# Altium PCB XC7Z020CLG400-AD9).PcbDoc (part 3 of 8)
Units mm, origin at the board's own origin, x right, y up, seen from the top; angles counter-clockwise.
Board outline 38 x 38 mm, 14 copper layers (Top Layer, GND02, ART03, PWR04, ART05, GND06, ART07, ART08, PWR09, ART10, GND11, ART12, PWR13, Bottom Layer); 276 components, 302 nets, 1684 pads, 1576 vias.
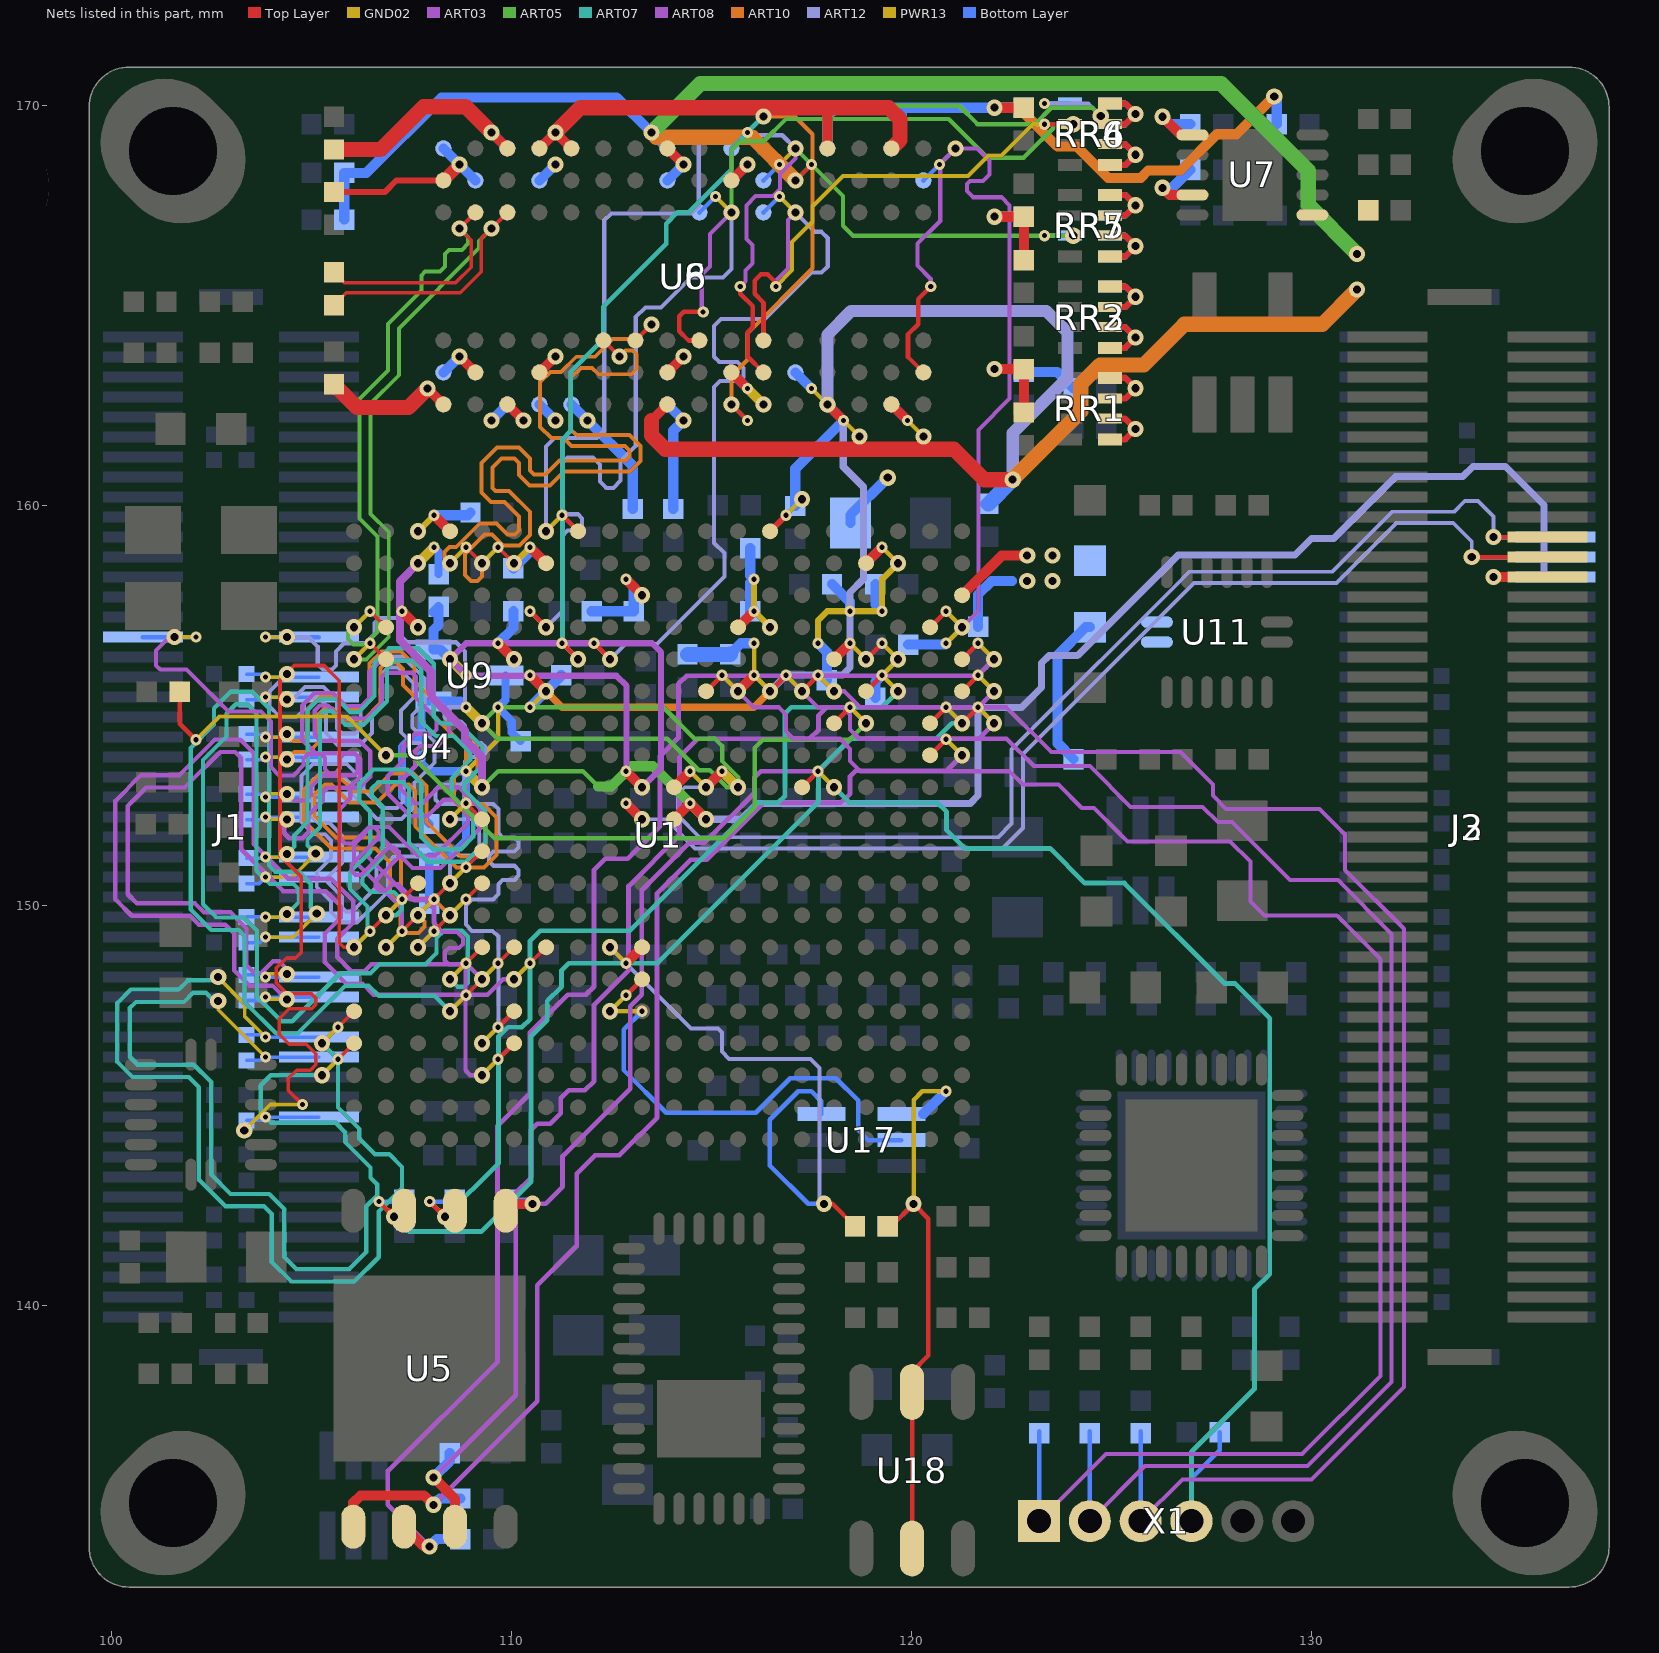
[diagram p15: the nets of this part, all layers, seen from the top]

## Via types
v1: diameter 0.406, hole 0.203, GND02 to PWR13, 466 vias
v2: diameter 0.279, hole 0.127, Top Layer to GND02, tented top, 373 vias
v3: diameter 0.406, hole 0.203, Top Layer to Bottom Layer, 324 vias
v4: diameter 0.279, hole 0.127, PWR13 to Bottom Layer, 207 vias
v5: diameter 0.279, hole 0.127, Top Layer to ART03, tented top, 41 vias
v6: diameter 0.279, hole 0.127, Top Layer to ART03, 40 vias
v7: diameter 0.279, hole 0.127, PWR13 to Bottom Layer, tented bottom, 39 vias
v8: diameter 0.279, hole 0.127, ART12 to Bottom Layer, 30 vias
v9: diameter 0.279, hole 0.127, Top Layer to GND02, 20 vias
v10: diameter 0.406, hole 0.203, Top Layer to Bottom Layer, tented both sides, 16 vias
v11: diameter 0.406, hole 0.203, ART03 to ART12, 11 vias
v12: diameter 0.406, hole 0.203, Top Layer to Bottom Layer, tented top, 9 vias

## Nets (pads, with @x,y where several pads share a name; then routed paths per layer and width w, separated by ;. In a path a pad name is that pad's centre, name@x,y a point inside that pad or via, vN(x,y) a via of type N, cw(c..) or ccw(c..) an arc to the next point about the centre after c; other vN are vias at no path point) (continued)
ADDR3-DQS2_N: U1.T2 U8.G3 | length 18.3
  Top Layer w0.089: v2(108.865,158.965) U1.T2@109.265,158.565 ; U8.G3@113.1,164.135 v3(113.5,164.535)
  ART10 w0.099: v1(108.465,158.565) 108.331,158.699 108.331,158.852 108.452,158.973 108.62,158.973 109.207,159.56 109.629,159.56 109.906,159.283 110.084,159.283 110.188,159.388 110.188,159.738 109.827,160.099 109.486,160.099 109.248,160.337 109.248,161.074 109.636,161.463 110.19,161.463 110.465,161.188 110.465,160.884 110.566,160.782 110.846,160.782 111.201,161.138 112.852,161.138 112.954,161.239 112.954,161.381 112.839,161.496 111.505,161.496 111.305,161.696 110.998,161.696 110.719,161.976 110.719,163.093 110.973,163.347 111.238,163.347 111.619,163.728 112.083,163.728 112.521,164.167 113.132,164.167 v3(113.5,164.535)
  GND02 w0.109: v1(108.465,158.565) v2(108.865,158.965)
ADDR3-DQS2_P: U1.R2 U8.F3 | length 18.3
  Top Layer w0.089: v2(109.665,158.965) U1.R2@110.065,158.565 ; U8.F3@112.3,164.135 v3(112.7,163.735)
  ART10 w0.099: v1(109.265,158.565) 109.265,158.236 109.149,158.121 108.986,158.121 108.839,158.267 108.839,158.801 109.321,159.283 109.514,159.283 109.791,159.007 110.198,159.007 110.465,159.273 110.465,159.853 109.942,160.376 109.601,160.376 109.525,160.452 109.525,160.96 109.751,161.186 110.076,161.186 110.188,161.074 110.188,160.769 110.452,160.505 110.96,160.505 111.316,160.861 112.967,160.861 113.231,161.125 113.231,161.496 112.954,161.773 111.622,161.773 111.481,161.914 111.481,163.195 111.735,163.449 112.014,163.449 112.172,163.291 112.999,163.291 113.132,163.424 113.132,163.779 113.03,163.881 112.846,163.881 v3(112.7,163.735)
  GND02 w0.109: v1(109.265,158.565) v2(109.665,158.965)
ADDR3-DQS3_N: R98.2 U1.W4 U8.B7 | length 19.7
  Top Layer w0.089: R98.2@105.562,165.84 105.82,165.583 108.61,165.583 108.991,165.964 108.991,166.644 v3(108.7,166.935) U8.B7@109.1,167.335 ; v2(106.465,157.365) U1.W4@106.865,156.965
  ART05 w0.099: v1(106.065,156.965) 105.918,156.818 105.918,156.667 106.045,156.54 106.35,156.54 106.655,156.845 106.655,159.233 106.2,159.687 106.2,162.672 106.909,163.38 106.909,164.552 107.747,165.39 107.747,165.76 107.841,165.855 108.211,165.855 108.337,165.98 108.337,166.299 108.438,166.401 108.758,166.401 108.915,166.558 ; v3(108.7,166.935) 108.915,166.72 108.915,166.558 ; 108.915,166.562 108.915,166.558
  GND02 w0.109: v1(106.065,156.965) v2(106.465,157.365)
ADDR3-DQS3_P: R98.1 U1.W5 U8.C7 | length 19.7
  Top Layer w0.089: R98.1@105.562,165.02 105.868,165.326 108.717,165.326 109.248,165.857 109.248,166.683 v3(109.5,166.935) U8.C7@109.9,167.335 ; v2(106.465,156.565) U1.W5@106.865,156.165
  ART05 w0.099: v1(106.065,156.165) 106.37,156.165 106.931,156.727 106.931,159.347 106.477,159.802 106.477,162.557 107.185,163.266 107.185,164.437 109.192,166.444 109.192,166.627 v3(109.5,166.935)
  GND02 w0.109: v1(106.065,156.165) v2(106.465,156.565)
ADDR3-ODT0: RR6.8 U1.N5 U6.K1 U8.K1 | length 39.5
  Top Layer w0.114: v2(111.265,156.565) v1(111.665,156.165) ; v1(115.5,162.535) v2(115.9,162.135)
  ART05 w0.109: v1(116.3,169.735) 116.567,170.002 121.191,170.002 121.649,169.545 123.088,169.545 123.495,169.951 124.528,169.951 v11(124.731,169.748)
  ART10 w0.109: v1(115.5,162.535) 115.5,163.252 115.9,163.652 115.9,164.313 117.526,165.938 117.526,169.291 117.082,169.735 v1(116.3,169.735)
  ART12 w0.102: v8(123.325,170.061) 124.419,170.061 v11(124.731,169.748)
  GND02 w0.109: v2(111.265,156.565) v1(111.665,156.165) ; v1(115.5,162.535) v2(115.9,162.135)
  ART07 w0.119: v1(111.665,156.165) 111.277,156.553 111.277,161.671 111.481,161.874 111.481,163.347 112.293,164.16 112.293,164.973 113.868,166.548 113.868,167.056 114.148,167.335 114.427,167.335 115.494,168.402 115.494,168.929 v1(116.3,169.735)
  PWR13 w0.114: v7(115.9,169.335) v1(116.3,169.735)
  Bottom Layer w0.114: U6.K1@115.5,168.935 v7(115.9,169.335) ; v8(123.325,170.061) RR6.8@123.96,170.061
ADDR3-RAS: RR6.7 U1.P4 U6.J3 U8.J3 | length 34.9
  Top Layer w0.114: v2(110.465,157.365) v1(110.865,156.965) ; U8.J3@114.7,164.135 114.427,164.135 114.198,164.363 114.198,164.744 114.305,164.851 v5(114.792,164.851)
  ART03 w0.102: v5@114.757,164.851 114.757,165.786 114.96,165.989 114.96,166.795 v1(115.5,167.335)
  ART05 w0.109: v1(115.5,167.335) 115.5,168.891 115.722,169.113 116.307,169.113 116.865,169.672 120.929,169.672 121.895,168.707 122.809,168.707 123.643,169.541 v11(124.046,169.541)
  ART12 w0.102: v1(110.865,156.965) 111.258,157.358 111.258,159.239 111.404,159.385 111.658,159.385 111.76,159.487 111.76,159.69 111.658,159.791 111.385,159.791 111.258,159.918 111.258,161.067 111.404,161.214 112.039,161.214 112.217,161.036 112.217,160.604 112.37,160.452 112.547,160.452 112.725,160.63 112.725,161.112 113.106,161.493 113.106,164.719 113.348,164.961 113.734,164.961 114.484,165.71 115.291,165.71 115.5,165.919 v1(115.5,167.335) ; v8(123.325,169.541) v11(124.046,169.541)
  GND02 w0.109: v2(110.465,157.365) v1(110.865,156.965)
  PWR13 w0.114: v7(115.1,167.735) v1(115.5,167.335)
  Bottom Layer w0.114: U6.J3@114.7,167.335 v7(115.1,167.735) ; v8(123.325,169.541) RR6.7@123.96,169.541
ADDR3-RESET: R67.1 U1.B4 U6.T2 U8.T2 | length 24.7
  Top Layer w0.114: U8.T2@120.3,163.335 119.913,163.722 119.913,164.287 120.167,164.541 120.167,165.171 v5(120.482,165.486) ; U1.B4@120.465,156.965 v2(120.865,157.365)
  ART03 w0.102: v5(120.482,165.486) 120.482,165.674 120.148,166.008 120.148,166.554 120.719,167.125 120.719,168.555 v1(121.1,168.935) 121.641,168.935 121.955,168.621 121.955,168.284 121.793,168.123 121.463,168.123 121.387,168.046 121.387,167.869 121.539,167.716 122.25,167.716 122.453,167.513 122.453,162.681 121.672,161.9 121.672,157.372 v1(121.265,156.965)
  GND02 w0.109: v2(120.865,157.365) v1(121.265,156.965)
  PWR13 w0.114: v7(120.7,168.535) v1(121.1,168.935) ; v4(120.865,156.565) v1(121.265,156.965)
  Bottom Layer w0.114: U6.T2@120.3,168.135 v7(120.7,168.535)
  Bottom Layer w0.254: R67.1@119.917,156.532 120.832,156.532 v4(120.865,156.565)
ADDR3-S0: RR5.6 U1.N1 U6.L2 U8.L2 | length 34.5
  Top Layer w0.114: v2(111.265,159.765) U1.N1@111.665,159.365 ; v5(115.719,165.486) 115.719,165.306 116.037,164.989 116.037,164.475 115.91,164.348 115.91,163.725 U8.L2@116.3,163.335
  ART03 w0.102: v5(115.719,165.486) 115.849,165.615 115.849,165.887 116.027,166.065 116.027,166.522 115.875,166.675 115.875,167.513 116.103,167.742 116.535,167.742 116.713,167.919 116.713,168.3 117.1,168.687 v1(117.1,168.935)
  ART05 w0.109: v1(117.1,168.935) 118.288,167.747 118.288,167.005 118.538,166.755 v11(124.046,166.755)
  ART12 w0.102: v1(110.865,159.365) 110.865,161.487 111.074,161.696 112.141,161.696 112.319,161.874 112.319,167.132 112.497,167.31 114.503,167.31 114.681,167.488 114.681,169.088 114.859,169.266 116.769,169.266 v1(117.1,168.935) ; v8(123.325,166.755) v11(124.046,166.755)
  GND02 w0.109: v1(110.865,159.365) v2(111.265,159.765)
  PWR13 w0.114: v7(116.7,168.535) v1(117.1,168.935)
  Bottom Layer w0.114: U6.L2@116.3,168.135 v7(116.7,168.535) ; v8(123.325,166.755) RR5.6@123.96,166.755
ADDR3-WE: RR4.6 U1.M5 U6.L3 U8.L3 | length 32.8
  Top Layer w0.114: v2(112.065,156.565) v1(112.465,156.165) ; U8.L3@116.3,164.135 116.3,165.081 116.078,165.303 116.078,165.633 116.23,165.786 116.408,165.786 116.608,165.586 v5(116.608,165.486) ; v6(123.325,169.541) RR4.6@123.96,169.541
  ART03 w0.102: v5(116.608,165.486) 116.608,165.63 116.916,165.938 116.916,167.151 v1(117.1,167.335)
  ART12 w0.102: v1(112.465,156.165) 112.845,156.546 113.638,156.546 115.322,158.23 115.322,158.82 115.068,159.074 115.068,162.972 115.214,163.119 115.697,163.119 115.799,163.22 115.799,163.449 115.646,163.601 115.195,163.601 115.068,163.728 115.068,164.496 115.24,164.668 116.332,164.668 117.5,165.837 117.754,165.837 117.907,165.989 117.907,166.7 117.754,166.853 117.582,166.853 v1(117.1,167.335)
  GND02 w0.102: v5(116.608,165.486) 117.018,165.895 117.018,166.599 117.526,167.107 117.526,167.488 118.288,168.25 121.412,168.25 121.92,168.758 122.25,168.758 123.034,169.541 v6(123.325,169.541)
  GND02 w0.109: v2(112.065,156.565) v1(112.465,156.165)
  PWR13 w0.114: v7(116.7,167.735) v1(117.1,167.335)
  Bottom Layer w0.114: U6.L3@116.3,167.335 v7(116.7,167.735)
ADDRVREF: C49.1 C66.1 C75.1 C76.1 C97.1 C101.1 C102.1 U1.H6 U1.P6 U6.H1 U6.M8 U7.1 U8.H1 U8.M8 | length 94.4
  Top Layer w0.114: v1(117.1,168.135) v2(117.5,168.535)
  Top Layer w0.254: v2(110.465,155.765) v1(110.865,155.365) ; 113.5,162.135 U8.H1@113.9,162.535 ; U1.H6@115.665,155.365 v2(116.065,155.765)
  Top Layer w0.381: 113.5,162.135 113.5,161.76 113.843,161.417 121.056,161.417 121.818,160.655 v3(122.53,160.655)
  ART05 w0.381: v3(113.5,169.335) 114.721,170.556 127.741,170.556 129.921,168.377 129.921,167.519 v3(131.14,166.3)
  ART10 w0.178: v1(110.865,155.365) 111.265,154.965 116.065,154.965 v1(116.465,155.365)
  ART10 w0.381: v3(113.5,169.335) 113.62,169.215 116.02,169.215 v1(117.1,168.135) ; v3(122.53,160.655) 124.231,162.357 124.231,163.043 124.714,163.525 125.806,163.525 126.822,164.541 130.27,164.541 v3(131.14,165.411)
  ART12 w0.178: v1(116.465,155.365) 116.871,155.771 118.281,155.771 118.466,155.956 118.466,157.836 118.796,158.166 118.796,160.477 118.294,160.979 118.294,162.141 v1(117.9,162.535)
  ART12 w0.305: v1(117.9,162.535) 117.9,164.28 118.491,164.871 123.368,164.871 123.901,164.338 123.901,163.195 122.53,161.823 v3(122.53,160.655)
  GND02 w0.102: v1(117.1,168.135) v2(117.5,168.535)
  GND02 w0.109: v2(110.465,155.765) v1(110.865,155.365) ; v2(116.065,155.765) v1(116.465,155.365)
  PWR13 w0.114: v4(110.465,154.965) v1(110.865,155.365) ; v4(116.065,156.565) v2(116.065,155.765) v1(116.465,155.365) ; v7(117.5,162.935) v1(117.9,162.535)
  Bottom Layer w0.254: C102.1@105.82,167.157 C75.1@105.82,168.326 106.375,168.326 108.255,170.205 112.63,170.205 v3(113.5,169.335) U6.H1@113.9,168.935 ; v4(110.465,154.965) 111.245,155.745 C66.1@111.245,155.765 ; C49.1@115.468,156.293 115.74,156.565 v4(116.065,156.565) ; U6.M8@117.1,163.335 v7(117.5,162.935)
  Bottom Layer w0.381: C76.1@114.402,156.286 115.461,156.286 C49.1@115.468,156.293 ; C101.1@121.92,160.049 121.924,160.049 v3(122.53,160.655)
AEN_IB: R27.2 R144.1 U17.4 U18.2 U18.5 | length 15
  Top Layer w0.114: R27.2@119.409,141.986 119.488,141.986 v3(120.053,142.551) 120.421,142.183 120.421,138.76 120.015,138.354 U18.2@120.015,137.849 U18.5@120.015,133.931
  PWR13 w0.114: v3(120.053,142.551) 120.053,145.148 120.27,145.365 v4(120.865,145.365)
  Bottom Layer w0.114: R144.1@119.409,141.986 119.488,141.986 v3(120.053,142.551)
  Bottom Layer w0.254: U17.4@120.295,144.795 v4(120.865,145.365)
AEN_IB_DIR: U1.L15 U17.5 | length 12.4
  Top Layer w0.114: v2(112.865,147.765) U1.L15@113.265,148.165
  GND02 w0.109: v1(112.465,147.365) v2(112.865,147.765)
  PWR13 w0.114: v1(112.465,147.365) v4(113.265,147.365)
  Bottom Layer w0.114: v4(113.265,147.365) 112.801,146.901 112.801,145.898 113.868,144.831 116.103,144.831 116.967,145.694 118.11,145.694 118.669,145.136 118.669,144.399 118.923,144.145 U17.5@119.745,144.145
AEN_IB_FPGA: R27.1 U1.L14 U17.3 | length 17.3
  Top Layer w0.114: v3(117.816,142.551) 118.024,142.551 R27.1@118.589,141.986
  Top Layer w0.254: v2(112.865,148.565) U1.L14@113.265,148.965
  ART12 w0.102: v1(112.465,148.965) 114.491,146.939 115.164,146.939 115.265,146.837 115.265,146.355 115.443,146.177 117.475,146.177 117.703,145.949 v3@117.703,142.664
  ART12 w0.114: v3@117.703,142.664 v3(117.816,142.551)
  GND02 w0.109: v1(112.465,148.965) v2(112.865,148.565)
  Bottom Layer w0.114: U17.3@117.745,144.795 117.745,145.12 117.5,145.365 117.171,145.365 116.459,144.653 116.459,143.51 117.418,142.551 v3(117.816,142.551)
AGND: C34.1 C35.2 C36.1 J2.38 J3.38 R124.2 U1.J10 U1.K10 U4.A1 U9.3 | length 58.7
  Top Layer w0.254: U1.K10@114.065,152.165 v2(114.465,152.565) v1(114.865,152.165) ; v3(134.548,158.219) J3.38@135.9,158.219
  ART03 w0.203: v1(107.665,158.565) 107.213,158.113 107.213,156.642 108.001,155.854 108.001,155.219 108.839,154.381 108.839,154.153 109.265,153.727 v1(109.265,152.965)
  ART05 w0.109: v1(109.265,152.965) 109.665,153.365 111.785,153.365 112.166,152.984
  ART05 w0.254: 112.166,152.984 112.497,152.984 113.005,153.492 113.538,153.492 v1(114.865,152.165)
  ART12 w0.178: v1(114.865,152.165) 115.741,152.165 116.135,152.559 121.469,152.559 121.666,152.756 121.666,154.813 121.812,154.959 122.751,154.959 123.253,155.461 123.253,156.07 123.444,156.261 124.155,156.261 126.67,158.775 129.591,158.775 129.997,159.182 130.556,159.182 132.105,160.731 133.782,160.731 134.036,160.985 134.849,160.985 135.811,160.023 135.811,158.219 v3(134.548,158.219)
  GND02 w0.254: v2(114.465,152.565) v1(114.865,152.165)
  PWR13 w0.114: v4(108.865,153.365) 109.665,154.165 v4(109.665,154.965)
  PWR13 w0.254: v1(107.665,158.565) v4(108.065,158.965) ; v4(108.865,153.365) v1(109.265,152.965)
  Bottom Layer w0.203: U4.A1@107.75,153.775 107.75,153.565 107.95,153.365 v4(108.865,153.365) 108.865,151.638 108.454,151.228 C35.2@107.946,151.228 R124.2@107.946,150.053 ; v4(108.065,158.965) 108.178,158.852 C34.1@108.178,158.294 ; U9.3@109.852,155.763 109.852,155.152 v4(109.665,154.965) 110.007,154.623 110.007,154.339 C36.1@110.227,154.119
  Bottom Layer w0.254: v3(134.548,158.219) J2.38@136.1,158.219
AHVDD_CA: C4.1 C5.1 C6.1 C7.1 C50.1 C52.1 C53.1 C55.1 C56.1 C57.1 C58.1 C59.1 C60.1 C61.1 C62.1 C63.1 C64.1 C65.1 C67.1 C68.1 C69.1 C70.1 C71.1 C73.1 C74.1 C99.2 C130.1 C131.1 R5.1 R62.1 R69.1 U1.A3 U1.D2 U1.E5 U1.G1 U1.H4 U1.L3 U1.P2 U1.R5 U1.U1 U1.V4 U6.A1 U6.A8 U6.B2 U6.C1 U6.C9 U6.D2 U6.D9 U6.E9 U6.H2 U6.H9 U6.K2 U6.K8 U6.N1 U6.N9 U6.R1 U6.R9 U8.A1 U8.A8 U8.B2 U8.C1 U8.C9 U8.D2 U8.D9 U8.E9 U8.H2 U8.H9 U8.K2 U8.K8 U8.N1 U8.N9 U8.R1 U8.R9 U11.7 U11.8 | length 107
  Top Layer w0.152: C55.1@105.562,167.846 106.835,167.846 107.124,168.135 U8.A8@108.3,168.135 ; U1.G1@116.465,159.365 v2(116.865,159.765)
  Top Layer w0.254: v2(107.265,157.365) v1(107.665,156.965) ; v3(107.9,162.935) U8.A1@108.3,162.535 ; v4(108.065,159.765) U1.U1@108.465,159.365 ; v3(108.7,163.735) U8.B2@109.1,163.335 ; v3(109.5,169.335) U8.C9@109.9,168.935 ; v2(109.665,156.565) v1(110.065,156.165) ; U8.C1@109.9,162.535 v3(110.3,162.135) ; v4(110.465,158.965) U1.P2@110.865,158.565 ; U8.D2@110.7,163.335 v3(111.1,163.735) ; U8.D9@110.7,168.935 v3(111.1,169.335) U8.E9@111.5,168.935 ; v2(112.865,158.165) v1(113.265,157.765) ; U8.H2@113.9,163.335 v3(114.3,163.735) ; U8.H9@113.9,168.935 v3(114.3,168.535) ; U8.K2@115.5,163.335 v7(115.9,162.935) ; U8.K8@115.5,168.135 v12(115.9,168.535) ; U1.H4@115.665,156.965 v2(116.065,157.365) ; U8.N1@117.9,162.535 v2(118.3,162.135) ; U8.N9@117.9,168.935 117.9,169.951 ; U1.E5@118.065,156.165 v2(118.465,156.565) ; U1.D2@118.865,158.565 v2(119.265,158.965) ; U8.R1@119.5,162.535 v2(119.9,162.135) ; U1.A3@121.265,157.765 122.257,158.757 v3(122.892,158.757) ; v3(122.076,163.42) C56.1@122.809,163.42 C60.1@122.809,162.335 ; v3(122.076,167.23) C58.1@122.809,167.23 C57.1@122.809,166.145 ; v3(122.076,169.955) C59.1@122.809,169.955
  Top Layer w0.305: U8.A8@108.3,168.135 v3(108.7,168.535)
  Top Layer w0.381: C99.2@105.562,163.039 106.143,162.458 107.423,162.458 v3(107.9,162.935) ; C69.1@105.562,168.91 106.731,168.91 107.798,169.977 108.858,169.977 v3(109.5,169.335) ; v3(111.1,169.335) 111.716,169.951 119.431,169.951 119.71,169.672 119.71,169.145 U8.R9@119.5,168.935
  ART10 w0.254: v3(122.076,169.955) 122.678,169.955 123.647,168.986 124.13,168.986 124.917,168.199 125.73,168.199 125.914,168.383 126.727,168.383 127.635,169.291 128.124,169.291 v3(129.07,170.237)
  GND02 w0.102: v1(107.665,159.365) v4(108.065,159.765)
  GND02 w0.109: v2(107.265,157.365) v1(107.665,156.965) ; v2(109.665,156.565) v1(110.065,156.165) ; v1(110.065,158.565) v4(110.465,158.965) ; v2(112.865,158.165) v1(113.265,157.765) ; v2(116.065,157.365) v1(116.465,156.965) ; v2(116.865,159.765) v1(117.265,160.165) ; v2(118.3,162.135) v1(118.7,161.735) ; v2(118.465,156.565) v1(118.865,156.165) ; v2(119.265,158.965) v1(119.665,158.565) ; v2(119.9,162.135) v1(120.3,161.735)
  GND02 w0.254: v7(115.9,162.935) v1(116.3,162.535)
  PWR13 w0.114: v7(115.9,162.935) v1(116.3,162.535) ; v2(118.3,162.135) v1(118.7,161.735) ; v2(119.9,162.135) v1(120.3,161.735)
  PWR13 w0.152: v1(107.665,159.365) v4(108.065,159.765) ; v2(109.665,156.565) v1(110.065,156.165) ; v1(110.065,158.565) v4(110.465,158.965) ; v2(112.865,158.165) v1(113.265,157.765) ; v4(116.065,158.165) v2(116.065,157.365) v1(116.465,156.965) ; v4(117.665,156.565) 117.665,157.137 117.893,157.365 v4(118.465,157.365) v4(119.265,157.365) 119.265,158.165 v1(119.665,158.565)
  Bottom Layer w0.114: R62.1@129.07,169.605 R62.1@129.13,169.545
  Bottom Layer w0.254: v4(108.065,159.765) 108.906,159.765 C68.1@108.975,159.834 ; U6.A8@108.3,163.335 v3(108.7,163.735) ; U6.A1@108.3,168.935 v3(108.7,168.535) U6.B2@109.1,168.135 ; v3(109.5,162.135) U6.C9@109.9,162.535 ; v3(109.5,169.335) U6.C1@109.9,168.935 ; v2(109.665,156.565) 110.049,156.949 C6.1@110.049,157.365 ; C62.1@110.049,158.437 110.465,158.853 v4(110.465,158.965) ; U6.D9@110.7,162.535 v3(111.1,162.135) ; U6.D2@110.7,168.135 v3(111.1,168.535) ; U6.E9@111.5,162.535 v3(111.9,162.135) 113.03,161.005 C64.1@113.03,159.922 ; C5.1@112.002,157.365 C61.1@113.058,157.365 113.058,157.972 v2(112.865,158.165) ; U6.H9@113.9,162.535 v3(114.3,162.135) 114.046,161.881 C74.1@114.046,159.922 ; U6.H2@113.9,168.135 v3(114.3,168.535) ; U6.K8@115.5,163.335 v7(115.9,162.935) ; U6.K2@115.5,168.135 v12(115.9,168.535) ; C70.1@115.971,157.365 115.971,158.071 v4(116.065,158.165) 115.971,158.259 C71.1@115.971,158.945 ; C7.1@117.094,159.998 117.094,160.929 v2(118.3,162.135) U6.N9@117.9,162.535 ; v4(117.665,156.565) 117.885,156.345 R69.1@117.885,155.643 ; U6.N1@117.9,168.935 117.9,169.735 118.12,169.955 119.761,169.955 ; C67.1@118.012,158.045 118.465,157.592 v4(118.465,157.365) ; C53.1@118.475,159.569 118.475,159.775 v3(119.405,160.706) ; C50.1@119.097,158.045 119.097,157.533 v4(119.265,157.365) ; U6.R9@119.5,162.535 v2(119.9,162.135) ; U6.R1@119.5,168.935 119.761,169.196 119.761,169.955 ; C63.1@121.665,156.975 121.665,157.784 122.003,158.122 122.511,158.122 ; v3(122.076,163.42) 122.74,163.42 C73.1@122.809,163.351 123.64,163.351 C65.1@124.05,162.941 ; v3(122.076,167.23) C52.1@122.809,167.23 ; C4.1@122.809,169.955 v3(122.076,169.955) 119.761,169.955 ; R5.1@124.05,153.67 123.654,154.066 123.654,156.267 124.357,156.97 C131.1@124.46,156.97 ; v3(129.07,170.237) 129.13,170.177 R62.1@129.13,169.545
  other v2: 110.465,158.965 108.065,159.765 115.9,162.935
  other v4: 109.665,156.565 112.865,158.165
  other v7: 118.3,162.135 119.9,162.135
  other v10: 122.892,158.122 123.527,158.122 123.527,158.757
AJTAG_TCK: R34.2 U1.F9 X1.4 | length 30.6
  Top Layer w0.114: U1.F9@117.265,152.965 v2(117.665,153.365)
  GND02 w0.109: v2(117.665,153.365) v1(118.065,152.965)
  ART07 w0.119: v1(118.065,152.965) 118.452,152.578 120.65,152.578 120.879,152.349 120.879,151.892 121.336,151.435 123.469,151.435 124.333,150.571 125.324,150.571 127.838,148.057 128.092,148.057 128.956,147.193 128.956,140.792 128.575,140.411 128.575,137.922 127,136.347 X1.4@127,134.62
  Bottom Layer w0.114: X1.4@127,134.62 127,135.693 127.702,136.395 R34.2@127.702,136.836
AJTAG_TDI: R32.2 U1.G6 X1.2 | length 41
  Top Layer w0.114: U1.G6@116.465,155.365 v2(116.865,155.765)
  ART03 w0.102: v1(117.265,155.365) 117.665,154.965 118.288,154.965 118.466,154.788 118.466,154.407 118.694,154.178 122.377,154.178 123.063,153.492 124.46,153.492 125.476,152.476 127.279,152.476 127.66,152.095 128.016,152.095 129.464,150.647 130.658,150.647 132.004,149.301 132.004,138.1 129.896,135.992 125.832,135.992 X1.2@124.46,134.62
  GND02 w0.109: v2(116.865,155.765) v1(117.265,155.365)
  Bottom Layer w0.114: X1.2@124.46,134.62 R32.2@124.46,136.864
AJTAG_TDO: R33.2 U1.F6 X1.3 | length 40.2
  Top Layer w0.114: U1.F6@117.265,155.365 v2(117.665,155.765)
  ART03 w0.102: v1(118.065,155.365) 118.32,155.365 118.72,154.965 122.377,154.965 123.495,153.848 126.721,153.848 127.533,153.035 127.533,152.756 127.864,152.425 130.2,152.425 130.835,151.79 130.835,150.901 132.309,149.428 132.309,137.973 129.997,135.661 126.771,135.661 X1.3@125.73,134.62
  GND02 w0.109: v2(117.665,155.765) v1(118.065,155.365)
  Bottom Layer w0.114: X1.3@125.73,134.62 R33.2@125.73,136.864
AJTAG_TMS: R31.2 U1.J6 X1.1 | length 43.7
  Top Layer w0.114: U1.J6@114.865,155.365 v2(115.265,155.765)
  ART03 w0.102: v1(115.665,155.365) 116.065,154.965 116.688,154.965 116.865,154.788 116.865,154.356 117.043,154.178 118.212,154.178 118.466,153.924 118.466,153.619 118.72,153.365 122.453,153.365 122.783,153.035 123.672,153.035 124.257,152.451 124.562,152.451 125.4,151.613 127.965,151.613 128.473,151.105 128.473,150.114 128.829,149.758 130.632,149.758 131.724,148.666 131.724,138.252 129.769,136.296 124.866,136.296 X1.1@123.19,134.62
  GND02 w0.109: v2(115.265,155.765) v1(115.665,155.365)
  Bottom Layer w0.114: X1.1@123.19,134.62 R31.2@123.19,136.864
APS-CLK: R59.2 U1.E7 | length 22.8
  Top Layer w0.114: R59.2@101.706,155.353 101.706,154.558 v2(102.111,154.153) ; U1.E7@118.065,154.565 v2(118.465,154.965)
  ART05 w0.109: v1(106.865,153.765) 107.499,153.765 109.576,151.689 115.316,151.689 116.078,152.451 116.078,153.949 116.281,154.153 118.453,154.153 v1(118.865,154.565)
  GND02 w0.102: v2(102.111,154.153) 102.695,154.737 105.893,154.737 v1(106.865,153.765)
  GND02 w0.109: v2(118.465,154.965) v1(118.865,154.565)
ASPI-CS: R60.2 U1.A7 U5.1 | length 22.5
  Top Layer w0.114: U1.A7@121.265,154.565 v2(121.665,154.965)
  Top Layer w0.254: U5.1@109.855,142.38 110.026,142.551 v3(110.528,142.551)
  GND02 w0.109: v2(121.665,154.965) v1(122.065,154.565)
  ART08 w0.119: v3(110.528,142.551) 110.852,142.551 111.277,142.977 111.277,143.739 112.966,145.428 112.966,147.485 113.259,147.777 113.259,150.393 114.452,151.587 114.833,151.587 116.078,152.832 116.078,153.213 116.23,153.365 117.678,153.365 118.491,154.178 121.678,154.178 v1(122.065,154.565)
  Bottom Layer w0.114: R60.2@109.855,142.65 110.429,142.65 v3(110.528,142.551)
ASPI-DQ0/MODE0: R53.2 U1.B8 U5.5 | length 32.1
  Top Layer w0.114: U1.B8@120.465,153.765 v2(120.865,154.165)
  Top Layer w0.254: U5.5@106.045,134.48 106.045,135.077 106.229,135.261 107.817,135.261 v3(108.052,135.026)
  Top Layer w0.381: U5.5@106.045,134.48 U5.5@106.045,134.715
  GND02 w0.109: v2(120.865,154.165) v1(121.265,153.765)
  ART08 w0.119: v3(108.052,135.026) 110.642,137.617 110.642,140.513 111.633,141.503 111.633,143.307 112.09,143.764 112.7,143.764 113.64,144.704 113.64,150.317 114.478,151.155 114.884,151.155 116.307,152.578 118.237,152.578 118.466,152.806 118.466,153.238 118.606,153.379 120.879,153.379 v1(121.265,153.765)
  Bottom Layer w0.254: v3(108.052,135.026) 108.21,135.185 R53.2@108.721,135.185
ASPI-DQ1/MODE1: R54.2 U1.D6 U5.2 | length 24.6
  Top Layer w0.114: v9(107.956,142.609) 108.185,142.38 U5.2@108.585,142.38 ; U1.D6@118.865,155.365 v2(119.265,155.765)
  Top Layer w0.254: U5.2@108.585,142.38 U5.2@108.585,142.462
  GND02 w0.102: v9(107.956,142.609) v1(108.337,142.228)
  GND02 w0.109: v2(119.265,155.765) v1(119.665,155.365)
  ART07 w0.119: v1(108.337,142.228) 109.677,143.568 109.677,146.736 109.906,146.964 110.261,146.964 110.465,147.168 110.465,149.123 110.719,149.377 112.954,149.377 116.154,152.578 116.662,152.578 116.84,152.756 116.84,154.813 116.992,154.965 119.265,154.965 v1(119.665,155.365)
  PWR13 w0.114: v9(107.956,142.609) v1(108.337,142.228)
  Bottom Layer w0.114: v9(107.956,142.609) 108.544,142.609 R54.2@108.585,142.65
  other v4: 107.956,142.609
ASPI-DQ2/MODE2: R55.2 U1.B7 U5.3 | length 26.3
  Top Layer w0.114: v9(106.686,142.609) 106.915,142.38 U5.3@107.315,142.38 ; U1.B7@120.465,154.565 v2(120.865,154.965)
  GND02 w0.102: v9(106.686,142.609) v1(107.067,142.228)
  GND02 w0.109: v2(120.865,154.965) v1(121.265,154.565)
  ART07 w0.119: v1(107.067,142.228) 107.436,141.859 109.245,141.859 110.49,143.104 110.49,146.736 110.896,147.142 110.896,147.625 111.252,147.98 111.252,148.387 111.43,148.565 113.64,148.565 117.678,152.603 117.678,153.391 118.466,154.178 120.625,154.178 121.012,154.565 v1(121.265,154.565)
  PWR13 w0.114: v9(106.686,142.609) v1(107.067,142.228)
  Bottom Layer w0.114: v9(106.686,142.609) 107.274,142.609 R55.2@107.315,142.65
  other v4: 106.686,142.609
ASPI-DQ3/MODE3: R58.2 U1.A6 U5.7 | length 33.1
  Top Layer w0.114: U1.A6@121.265,155.365 v2(121.665,155.765)
  Top Layer w0.254: v3(108.052,135.712) 108.585,135.179 U5.7@108.585,134.48
  GND02 w0.109: v2(121.665,155.765) v1(122.065,155.365)
  ART08 w0.119: v3(108.052,135.712) 110.109,137.77 110.109,142.824 110.49,143.205 110.49,144.399 110.642,144.551 110.967,144.551 111.23,144.814 111.23,145.189 111.43,145.39 111.836,145.39 112.065,145.618 112.065,147.523 112.928,148.387 112.928,150.495 114.198,151.765 114.198,153.721 114.655,154.178 117.45,154.178 117.678,154.407 117.678,154.762 117.881,154.965 121.665,154.965 v1(122.065,155.365)
  Bottom Layer w0.254: v3(108.052,135.712) 108.458,136.119 R58.2@108.458,136.32
ASPI-SCK/MODE4: R57.2 U1.A5 U5.6 | length 36.4
  Top Layer w0.114: U1.A5@121.265,156.165 v2(121.665,156.565)
  Top Layer w0.254: U5.6@107.315,134.48 v3@107.81,133.985
  GND02 w0.109: v2(121.665,156.565) v1(122.065,156.165)
  ART08 w0.119: v3(107.95,133.985) 106.909,135.026 106.909,135.865 109.652,138.608 109.652,144.501 110.465,145.313 110.465,146.837 111.404,147.777 111.862,147.777 112.065,147.98 112.065,150.901 112.344,151.181 112.903,151.181 113.716,151.994 113.716,153.746 114.173,154.203 114.173,155.55 114.376,155.753 121.653,155.753 v1(122.065,156.165)
  Bottom Layer w0.254: v3(107.95,133.985) 108.134,134.169 R57.2@108.721,134.169
ASPI-SCLK-FB/VCFG1: R52.2 U1.D5 | length 2.3
  Top Layer w0.114: U1.D5@118.865,156.165 v2(119.265,156.565)
  GND02 w0.109: v2(119.265,156.565) v1(119.665,156.165)
  PWR13 w0.114: v4(119.265,155.765) v1(119.665,156.165)
  Bottom Layer w0.254: R52.2@119.097,155.199 119.097,155.597 v4(119.265,155.765)
AVCC: C35.1 U1.J9 U4.B1 U9.1 | length 21.5
  Top Layer w0.254: U1.J9@114.865,152.965 v2(115.265,153.365)
  ART05 w0.109: v1@109.258,154.572 109.652,154.965 113.792,154.965 114.529,154.229 114.579,154.178 115.087,154.178 115.265,154 115.265,153.619 115.665,153.219 v1(115.665,152.965) 115.386,152.965 114.96,153.391 114.681,153.391 113.894,154.178 109.652,154.178 v1@109.258,154.572
  GND02 w0.254: v2(115.265,153.365) v1(115.665,152.965)
  PWR13 w0.254: v4(108.865,154.965) v1(109.265,154.565)
  Bottom Layer w0.203: U4.B1@107.667,154.175 U4.B1@107.75,154.175 ; C35.1@107.946,152.048 107.264,152.729 107.264,153.975 107.464,154.175 U4.B1@107.75,154.175 ; U9.1@108.052,155.113 107.75,155.113 U4.B1@107.75,154.175
  Bottom Layer w0.254: U9.1@108.052,155.113 108.717,155.113 v4(108.865,154.965)
AVINN: J2.39 J3.39 U1.L10 | length 31.2
  Top Layer w0.114: v3(134.007,158.719) J3.39@135.9,158.719
  Top Layer w0.254: v2(112.865,152.565) v1(113.265,152.165)
  ART12 w0.097: v1(113.265,152.165) 113.86,152.165 114.591,151.435 122.276,151.435 122.784,151.943 122.784,153.797 127.059,158.072 130.629,158.072 132.129,159.572 133.544,159.572 134.007,159.109 v3(134.007,158.719)
  GND02 w0.109: v2(112.865,152.565) v1(113.265,152.165)
  Bottom Layer w0.114: v3(134.007,158.719) J2.39@136.1,158.719
AVINP: J2.40 J3.40 U1.K9 | length 31.2
  Top Layer w0.114: v3(134.548,159.219) J3.40@135.9,159.219
  Top Layer w0.254: U1.K9@114.065,152.965 v2(114.465,153.365)
  ART12 w0.097: v1(114.865,152.965) 114.332,152.965 114.16,152.794 114.16,152.26 114.706,151.714 122.16,151.714 122.504,152.059 122.504,153.913 126.943,158.352 130.513,158.352 132.013,159.852 133.563,159.852 133.833,160.122 134.163,160.122 134.548,159.736 v3(134.548,159.219)
  GND02 w0.109: v2(114.465,153.365) v1(114.865,152.965)
  Bottom Layer w0.114: v3(134.548,159.219) J2.40@136.1,159.219
AVREF: C34.2 U1.L9 U9.2 | length 20.6
  Top Layer w0.254: v2(112.865,153.365) v1(113.265,152.965)
  ART03 w0.152: v1(108.465,156.165) 108.866,156.566 112.674,156.566 113.513,156.566 113.741,156.337 113.741,155.651 113.741,153.441 v1(113.265,152.965) 112.878,153.352 112.878,155.499 112.624,155.753 108.877,155.753 v1(108.465,156.165)
  GND02 w0.109: v2(112.865,153.365) v1(113.265,152.965)
  PWR13 w0.254: v1(108.465,156.165) v4(108.865,155.765)
  Bottom Layer w0.254: C34.2@108.052,157.348 C34.2@108.178,157.474 108.178,157.022 108.052,156.896 U9.2@108.052,156.413 108.217,156.413 v4(108.865,155.765)
AVTT: C2.1 C3.1 RR1.1 RR1.2 RR1.3 RR1.4 RR2.1 RR2.2 RR2.3 RR2.4 RR3.1 RR3.2 RR3.3 RR3.4 RR4.1 RR4.2 RR4.3 RR4.4 RR5.1 RR5.2 RR5.3 RR5.4 RR6.1 RR6.2 RR6.3 RR6.4 RR7.1 RR7.2 RR7.3 RR7.4 U7.6 U7.9 | length 24.4
  Top Layer w0.152: RR1.1@124.96,161.663 125.345,161.663 v3(125.603,161.921) 125.341,162.183 RR1.2@124.96,162.183 ; RR1.3@124.96,162.683 125.345,162.683 v3(125.603,162.941) 125.341,163.203 RR1.4@124.96,163.203 ; RR3.1@124.96,163.949 125.345,163.949 v3(125.603,164.207) 125.341,164.469 RR3.2@124.96,164.469 ; RR3.3@124.96,164.969 125.345,164.969 v3(125.603,165.227) 125.341,165.489 RR3.4@124.96,165.489 ; RR7.1@124.96,166.235 125.345,166.235 v3(125.603,166.493) 125.341,166.755 RR7.2@124.96,166.755 ; RR7.3@124.96,167.255 125.345,167.255 v3(125.603,167.513) 125.341,167.775 RR7.4@124.96,167.775 ; RR4.1@124.96,168.521 125.345,168.521 v3(125.603,168.779) 125.341,169.041 RR4.2@124.96,169.041 ; RR4.3@124.96,169.541 125.345,169.541 v3(125.603,169.799) 125.341,170.061 RR4.4@124.96,170.061
  Top Layer w0.254: v3(126.276,167.951) 126.452,167.775 U7.9@127.024,167.775 ; v3(126.276,169.729) 126.73,169.275 U7.6@127.024,169.275
  Bottom Layer w0.152: RR2.4@124.96,163.949 125.345,163.949 v3(125.603,164.207) 125.341,164.469 RR2.3@124.96,164.469 ; RR2.2@124.96,164.969 125.345,164.969 v3(125.603,165.227) 125.341,165.489 RR2.1@124.96,165.489 ; RR5.4@124.96,166.235 125.345,166.235 v3(125.603,166.493) 125.341,166.755 RR5.3@124.96,166.755 ; RR5.2@124.96,167.255 125.345,167.255 v3(125.603,167.513) 125.341,167.775 RR5.1@124.96,167.775 ; RR6.4@124.96,168.521 125.345,168.521 v3(125.603,168.779) 125.341,169.041 RR6.3@124.96,169.041 ; RR6.2@124.96,169.541 125.345,169.541 v3(125.603,169.799) 125.341,170.061 RR6.1@124.96,170.061
  Bottom Layer w0.254: v3(126.276,167.951) 126.52,167.951 C2.1@126.971,168.402 ; v3(126.276,169.729) 126.46,169.545 C3.1@126.971,169.545
B34_C0: J1.66 U1.R16 | length 26.3
  Top Layer w0.114: v2(109.665,146.965) U1.R16@110.065,147.365
  ART12 w0.102: v1(104.386,156.719) 104.926,156.719 105.156,156.489 105.156,156.032 105.283,155.905 105.512,155.905 105.613,156.007 105.613,156.362 105.816,156.566 106.35,156.566 106.578,156.794 106.578,157.074 106.705,157.201 107.137,157.201 107.264,157.074 107.264,156.718 107.391,156.591 108.61,156.591 108.839,156.362 108.839,155.072 108.732,154.965 108.438,154.965 108.331,154.859 108.331,154.716 108.438,154.61 108.732,154.61 108.839,154.503 108.839,154.183 108.946,154.076 109.24,154.076 109.347,153.97 109.347,153.827 109.24,153.721 108.946,153.721 108.839,153.614 108.839,153.137 108.737,153.035 108.229,153.035 108.102,152.908 108.102,152.654 108.204,152.552 109.543,152.552 109.67,152.425 109.67,151.821 109.777,151.714 110.072,151.714 110.178,151.608 110.178,151.465 110.072,151.359 109.55,151.359 109.444,151.252 109.444,151.11 109.55,151.003 110.072,151.003 110.178,150.896 110.178,150.754 110.072,150.647 109.777,150.647 109.67,150.541 109.67,150.292 109.543,150.165 109.017,150.165 108.864,150.012 108.864,149.53 109.017,149.377 109.525,149.377 109.67,149.232 109.67,146.971 v1(109.265,146.565)
  GND02 w0.109: v1(109.265,146.565) v2(109.665,146.965)
  PWR13 w0.089: v4(103.853,156.719) v1(104.386,156.719)
  Bottom Layer w0.114: v4(103.853,156.719) J1.66@105.182,156.719
B34_C1: J1.16 U1.R17 | length 26.9
  Top Layer w0.114: v2(109.665,146.165) U1.R17@110.065,146.565
  ART03 w0.102: v1(101.573,156.719) 101.449,156.719 101.117,156.388 101.117,156.007 101.219,155.905 101.879,155.905 102.921,154.864 103.734,154.864 103.988,154.61 103.988,153.467 104.191,153.264 104.546,153.264 104.8,153.518 104.8,153.69 104.907,153.797 105.232,153.797 105.334,153.695 105.334,153.416 105.435,153.314 105.588,153.314 105.715,153.441 105.715,153.695 105.816,153.797 106.096,153.797 106.223,153.67 106.223,153.238 105.969,152.984 105.969,152.679 105.709,152.42 105.709,151.694 105.842,151.562 106.026,151.562 106.427,151.963 106.578,151.963 106.679,151.863 106.679,151.712 106.338,151.371 105.997,151.03 105.997,150.879 106.097,150.778 106.248,150.778 106.589,151.119 106.93,151.46 107.081,151.46 107.181,151.36 107.181,151.209 106.841,150.868 106.599,150.627 106.599,150.476 106.7,150.375 106.851,150.375 107.017,150.541 107.167,150.541 107.569,150.139 107.848,150.139 108.052,149.936 108.052,149.581 108.28,149.352 108.636,149.352 108.788,149.2 108.788,149.047 108.687,148.946 108.433,148.946 108.331,148.844 108.331,148.641 108.433,148.539 108.744,148.539 108.846,148.438 108.846,145.891 108.972,145.765 v1(109.265,145.765)
  GND02 w0.109: v1(109.265,145.765) v2(109.665,146.165)
  PWR13 w0.102: v1(101.573,156.719) v4(102.111,156.719)
  Bottom Layer w0.114: J1.16@100.782,156.719 v4(102.111,156.719)
B34_L1_N: J1.69 R43.2 U1.T10 | length 27
  Top Layer w0.089: v2(108.865,152.565) U1.T10@109.265,152.165
  ART12 w0.097: v1(104.386,155.163) 104.526,155.163 104.837,155.473 105.297,155.473 105.639,155.132 105.639,154.432 105.766,154.305 106.096,154.305 106.233,154.442 106.233,154.899 106.477,155.143 106.477,155.919 106.793,156.235 107.278,156.235 107.823,155.691 107.823,155.078 107.518,154.773 107.518,154.457 107.62,154.356 107.823,154.356 108.077,154.102 108.077,153.58 107.569,153.072 107.569,152.487 107.253,152.171 106.64,152.171 106.02,152.792 106.02,153.01 105.766,153.264 105.156,153.264 105.029,153.137 105.029,152.211 105.17,152.07 105.45,152.07 105.766,151.754 105.766,151.074 105.41,150.718 105.41,150.585 105.766,150.23 105.766,149.962 105.867,149.86 106.02,149.86 106.629,150.47 106.629,151.195 106.945,151.511 108.421,151.511 108.675,151.257 109.017,151.257 109.195,151.435 109.195,151.968 108.998,152.165 v1(108.465,152.165)
  GND02 w0.109: v1(108.465,152.165) v2(108.865,152.565)
  PWR13 w0.089: v4(103.853,155.219) 104.329,155.219 v1(104.386,155.163)
  Bottom Layer w0.089: R43.2@103.378,155.153 103.787,155.153 v4(103.853,155.219) J1.69@105.182,155.219
B34_L1_P: J1.68 R43.1 U1.T11 | length 27
  Top Layer w0.089: v2(108.865,150.965) U1.T11@109.265,151.365
  ART12 w0.097: v1(104.386,155.798) 103.951,155.363 103.951,154.983 104.206,154.728 104.631,154.728 104.82,154.917 104.82,155.061 104.953,155.194 105.181,155.194 105.359,155.016 105.359,154.316 105.65,154.026 106.212,154.026 106.512,154.326 106.512,154.783 106.756,155.027 106.756,155.804 106.909,155.956 107.163,155.956 107.544,155.575 107.544,155.194 107.239,154.889 107.239,154.342 107.504,154.076 107.707,154.076 107.798,153.986 107.798,153.695 107.29,153.187 107.29,152.603 107.137,152.451 106.756,152.451 106.299,152.908 106.299,153.125 105.881,153.543 105.04,153.543 104.75,153.252 104.75,152.095 105.054,151.79 105.334,151.79 105.486,151.638 105.486,151.189 105.131,150.834 105.131,150.47 105.484,150.117 105.484,149.848 105.751,149.581 106.135,149.581 106.909,150.354 106.909,151.079 107.061,151.232 108.306,151.232 108.465,151.072 v1(108.465,150.565)
  GND02 w0.109: v1(108.465,150.565) v2(108.865,150.965)
  PWR13 w0.089: v4(103.853,155.719) 104.307,155.719 v1(104.386,155.798)
  Bottom Layer w0.089: R43.1@103.378,155.793 103.779,155.793 v4(103.853,155.719) J1.68@105.182,155.719
B34_L2_N: J1.72 R47.2 U1.U12 | length 27.1
  Top Layer w0.089: v2(108.065,150.165) U1.U12@108.465,150.565
  ART10 w0.099: v1(104.386,153.663) 104.573,153.85 104.936,153.85 105.181,154.096 105.181,154.802 105.319,154.94 105.526,154.94 105.803,154.663 106.327,154.663 106.731,155.067 106.731,155.945 106.871,156.086 107.124,156.086 107.292,155.918 107.292,155.522 108.867,153.947 108.867,153.508 108.562,153.203 108.562,152.616 108.905,152.273 109.172,152.273 109.347,152.098 109.347,151.384 109.195,151.232 108.737,151.232 107.871,152.098 107.871,152.997 107.554,153.314 106.985,153.314 106.528,152.857 106.07,152.857 105.613,153.314 105.222,153.314 104.803,152.896 104.803,152.133 105.501,151.435 106.604,151.435 106.959,151.079 106.959,150.281 107.219,150.021 107.219,149.498 107.391,149.327 107.671,149.327 107.823,149.479 107.823,149.607 v1(107.665,149.765)
  GND02 w0.109: v1(107.665,149.765) v2(108.065,150.165)
  PWR13 w0.089: v4(103.853,153.719) 104.329,153.719 v1(104.386,153.663)
  Bottom Layer w0.089: R47.2@103.378,153.655 103.789,153.655 v4(103.853,153.719) J1.72@105.182,153.719
B34_L2_P: J1.71 R47.1 U1.T12 | length 27
  Top Layer w0.089: v2(108.865,150.165) U1.T12@109.265,150.565
  ART10 w0.099: v1(104.386,154.298) 104.556,154.127 104.75,154.127 104.905,154.282 104.905,154.917 105.204,155.217 105.641,155.217 105.918,154.94 106.212,154.94 106.454,155.182 106.454,156.06 106.756,156.362 107.239,156.362 107.569,156.032 107.569,155.636 109.144,154.062 109.144,153.393 108.839,153.088 108.839,152.73 109.019,152.55 109.286,152.55 109.624,152.212 109.624,151.269 109.309,150.955 108.623,150.955 107.594,151.983 107.594,152.883 107.439,153.038 107.099,153.038 106.642,152.58 105.956,152.58 105.499,153.038 105.336,153.038 105.08,152.781 105.08,152.248 105.616,151.712 106.718,151.712 107.236,151.194 107.236,150.396 107.442,150.19 108.04,150.19 v1(108.465,149.765)
  GND02 w0.109: v1(108.465,149.765) v2(108.865,150.165)
  PWR13 w0.089: v4(103.853,154.219) 104.307,154.219 v1(104.386,154.298)
  Bottom Layer w0.089: R47.1@103.378,154.295 103.777,154.295 v4(103.853,154.219) J1.71@105.182,154.219
B34_L3_N: J1.75 R50.2 U1.V13 | length 27.1
  Top Layer w0.089: v2(107.265,149.365) U1.V13@107.665,149.765
  GND02 w0.109: v1(106.865,148.965) v2(107.265,149.365)
  ART08 w0.107: v1(104.386,152.163) 104.318,152.095 104.318,151.816 104.445,151.689 104.775,151.689 104.927,151.841 104.927,152.273 105.283,152.629 105.283,152.832 105.405,152.954 106.199,152.954 106.466,153.221 106.466,153.865 106.204,154.127 105.232,154.127 105.08,154.28 105.08,154.883 105.208,155.011 105.409,155.011 105.734,154.686 106.382,154.686 106.756,155.061 106.756,155.721 106.864,155.829 107.518,155.829 107.615,155.732 107.615,155.199 108.128,154.686 108.128,154.407 108.026,154.305 107.588,154.305 107.285,154.002 107.285,153.621 106.909,153.245 106.909,152.806 107.467,152.248 107.899,152.248 108.306,152.654 108.56,152.654 108.91,152.303 108.91,152.071 108.096,151.257 107.652,151.257 106.935,151.973 106.501,151.973 106.065,151.538 106.065,151.135 107.264,149.936 v2(107.265,149.365) v1(106.865,148.965)
  PWR13 w0.089: v4(103.853,152.219) 103.909,152.163 v1(104.386,152.163)
  Bottom Layer w0.089: R50.2@103.378,152.156 103.79,152.156 v4(103.853,152.219) J1.75@105.182,152.219
B34_L3_P: J1.74 R50.1 U1.U13 | length 27.1
  Top Layer w0.089: v2(108.065,149.365) U1.U13@108.465,149.765
  GND02 w0.109: v1(107.665,148.965) v2(108.065,149.365)
  ART08 w0.107: v1(104.386,152.798) 104.55,152.634 104.85,152.634 104.973,152.757 104.973,152.96 105.277,153.264 106.07,153.264 106.156,153.349 106.156,153.737 106.075,153.817 105.104,153.817 104.77,154.151 104.77,155.011 105.08,155.321 105.537,155.321 105.862,154.996 106.253,154.996 106.446,155.189 106.446,155.849 106.736,156.139 107.647,156.139 107.925,155.861 107.925,155.327 108.438,154.814 108.438,154.278 108.155,153.995 107.716,153.995 107.594,153.873 107.594,153.492 107.218,153.116 107.218,152.935 107.596,152.557 107.771,152.557 108.177,152.964 108.688,152.964 109.22,152.432 109.22,151.943 108.224,150.947 107.523,150.947 106.807,151.663 106.629,151.663 106.426,151.46 106.426,151.213 107.474,150.165 107.95,150.165 108.077,150.038 108.077,149.377 v1(107.665,148.965)
  PWR13 w0.089: v4(103.853,152.719) 103.932,152.798 v1(104.386,152.798)
  Bottom Layer w0.089: R50.1@103.378,152.796 103.776,152.796 v4(103.853,152.719) J1.74@105.182,152.719
B34_L4_N: J1.78 R94.2 U1.W13 | length 27
  Top Layer w0.089: v2(106.465,149.365) U1.W13@106.865,149.765
  GND02 w0.109: v1(106.065,148.965) v2(106.465,149.365)
  ART07 w0.107: v1(105.105,151.308) 104.97,151.443 104.902,151.511 104.902,151.657 105.212,151.967 105.212,154.761 105.315,154.864 105.512,154.864 105.847,154.529 106.3,154.529 106.888,155.116 106.888,155.955 107.062,156.129 107.542,156.129 107.747,155.924 107.747,154.608 108.106,154.249 108.558,154.249 108.966,153.841 108.966,153.645 108.504,153.182 108.504,152.782 108.988,152.297 108.993,152.297 109.042,152.248 109.042,151.721 108.736,151.414 108.047,151.414 107.747,151.714 107.747,153.06 107.4,153.407 106.544,153.407 106.197,153.06 106.197,152.629 106.472,152.354 106.472,151.354 105.964,150.846 105.964,150.424 106.401,149.987 106.401,149.301 v1(106.065,148.965)
  PWR13 w0.089: v4(103.853,150.719) 104.517,150.719 v1(105.105,151.308)
  Bottom Layer w0.089: R94.2@103.378,150.556 103.69,150.556 v4(103.853,150.719) J1.78@105.182,150.719
B34_L4_P: J1.77 R94.1 U1.V12 | length 27
  Top Layer w0.089: v2(107.265,150.165) U1.V12@107.665,150.565
  GND02 w0.109: v1(106.865,149.765) v2(107.265,150.165)
  ART07 w0.107: v1(104.386,151.298) 104.572,151.484 104.572,151.765 104.902,152.095 104.902,154.889 105.186,155.174 105.64,155.174 105.975,154.838 106.172,154.838 106.578,155.245 106.578,156.083 106.934,156.439 107.671,156.439 108.057,156.053 108.057,154.736 108.234,154.559 108.687,154.559 109.276,153.97 109.276,153.516 108.814,153.054 108.814,152.91 109.116,152.607 109.121,152.607 109.352,152.376 109.352,151.592 108.864,151.105 107.918,151.105 107.437,151.586 107.437,152.932 107.272,153.097 106.672,153.097 106.507,152.932 106.507,152.757 106.782,152.483 106.782,151.225 106.274,150.717 106.274,150.552 106.479,150.347 107.056,150.347 107.264,150.139 107.264,149.911 107.118,149.765 v1(106.865,149.765)
  PWR13 w0.089: v4(103.853,151.219) 104.307,151.219 v1(104.386,151.298)
  Bottom Layer w0.089: R94.1@103.378,151.196 103.83,151.196 v4(103.853,151.219) J1.77@105.182,151.219
B34_L5_N: J1.81 R97.2 U1.T15 | length 27
  Top Layer w0.089: v2(108.865,147.765) U1.T15@109.265,148.165
  GND02 w0.109: v1(108.465,147.365) v2(108.865,147.765)
  ART07 w0.107: 104.983,149.957 v1(105.131,149.809) ; 104.983,149.957 104.983,150.547 104.675,150.856 104.089,150.856 103.937,151.008 103.937,154.94 103.525,155.351 102.977,155.351 102.565,154.94 102.565,154.534 101.981,153.949 101.981,149.911 102.494,149.398 103.18,149.398 103.327,149.25 103.327,147.599 104.12,146.807 104.649,146.807 105.848,148.006 106.426,148.006 106.68,147.752 108.078,147.752 v1(108.465,147.365)
  PWR13 w0.089: v4(103.853,149.219) 104.541,149.219 v1(105.131,149.809)
  Bottom Layer w0.089: R97.2@103.378,149.083 103.717,149.083 v4(103.853,149.219) J1.81@105.182,149.219
B34_L5_P: J1.80 R97.1 U1.T14 | length 27.1
  Top Layer w0.089: v2(108.865,148.565) U1.T14@109.265,148.965
  GND02 w0.109: v1(108.465,148.165) v2(108.865,148.565)
  ART07 w0.107: v1(104.386,149.798) 104.673,150.086 104.673,150.419 104.546,150.546 103.961,150.546 103.627,150.88 103.627,154.812 103.397,155.042 103.105,155.042 102.875,154.812 102.875,154.234 102.291,153.65 102.291,150.039 102.622,149.708 103.308,149.708 103.637,149.379 103.637,147.728 104.248,147.117 104.521,147.117 105.72,148.316 106.478,148.316 106.702,148.539 107.848,148.539 108.128,148.819 108.128,149.2 108.306,149.377 108.763,149.377 108.907,149.233 108.907,148.074 108.814,147.98 108.65,147.98 v1(108.465,148.165)
  PWR13 w0.089: v4(103.853,149.719) 104.307,149.719 v1(104.386,149.798)
  Bottom Layer w0.089: R97.1@103.378,149.723 v4@103.849,149.723 ; v4(103.853,149.719) J1.80@105.182,149.719
B34_L6_N: J1.84 R107.2 U1.R14 | length 27
  Top Layer w0.089: v2(109.665,148.565) U1.R14@110.065,148.965
  GND02 w0.109: v1(109.265,148.165) v2(109.665,148.565)
  ART08 w0.107: v1(104.386,147.663) 104.37,147.663 104.027,148.006 103.448,148.006 103.068,148.385 103.068,149.306 102.845,149.53 102.184,149.53 101.961,149.753 100.506,149.753 100.096,150.163 100.096,152.624 100.741,153.269 101.7,153.269 102.589,154.158 103.221,154.158 103.556,153.822 103.556,151.543 104.421,150.678 105.488,150.678 106.047,150.119 106.047,149.582 105.644,149.179 105.644,148.718 105.996,148.366 106.324,148.366 106.497,148.539 108.891,148.539 v1(109.265,148.165)
  PWR13 w0.089: v4(103.853,147.719) 103.909,147.663 v1(104.386,147.663)
  Bottom Layer w0.089: R107.2@103.378,147.635 103.769,147.635 v4(103.853,147.719) J1.84@105.182,147.719
B34_L6_P: J1.83 R107.1 U1.P14 | length 27
  Top Layer w0.089: v2(110.465,148.565) U1.P14@110.865,148.965
  GND02 w0.109: v1(110.065,148.165) v2(110.465,148.565)
  ART08 w0.107: v1(104.386,148.298) 104.386,148.421 104.191,148.615 104.038,148.615 103.739,148.316 103.576,148.316 103.378,148.514 103.378,149.435 102.973,149.84 102.313,149.84 102.089,150.063 100.635,150.063 100.406,150.292 100.406,152.495 100.87,152.959 101.829,152.959 102.718,153.848 103.092,153.848 103.246,153.694 103.246,151.414 104.292,150.368 105.359,150.368 105.737,149.99 105.737,149.711 105.334,149.308 105.334,148.59 105.867,148.057 106.274,148.057 106.553,147.777 109.398,147.777 109.786,148.165 v1(110.065,148.165)
  PWR13 w0.089: v4(103.853,148.219) 103.932,148.298 v1(104.386,148.298)
  Bottom Layer w0.089: R107.1@103.378,148.275 103.797,148.275 v4(103.853,148.219) J1.83@105.182,148.219
B34_L7_N: J1.87 R110.2 U1.Y17 | length 27
  Top Layer w0.089: v2(105.665,146.165) U1.Y17@106.065,146.565
  GND02 w0.109: v1(105.265,145.765) v2(105.665,146.165)
  ART07 w0.107: v1(102.667,147.625) 102.565,147.625 102.362,147.828 102.038,147.828 101.81,147.599 100.609,147.599 100.457,147.447 100.457,146.228 100.655,146.03 102.059,146.03 102.494,145.594 102.494,143.283 102.978,142.799 103.943,142.799 104.318,142.424 104.318,141.224 104.625,140.917 105.941,140.917 106.37,141.346 106.37,142.489 106.642,142.761 106.642,143.04 106.477,143.205 106.477,143.46 105.842,144.095 105.842,144.342 105.607,144.577 103.988,144.577 103.734,144.831 103.734,145.517 103.982,145.765 v1(105.265,145.765)
  PWR13 w0.089: v1(102.667,147.625) 102.667,147.405 v4(103.853,146.219)
  Bottom Layer w0.089: R110.2@103.378,146.136 103.77,146.136 v4(103.853,146.219) J1.87@105.182,146.219
B34_L7_P: J1.86 R110.1 U1.Y16 | length 27
  Top Layer w0.089: v2(105.665,146.965) U1.Y16@106.065,147.365
  GND02 w0.109: v1(105.265,146.565) v2(105.665,146.965)
  ART07 w0.107: v1(102.667,148.219) 102.586,148.138 101.91,148.138 101.681,147.909 100.481,147.909 100.147,147.575 100.147,146.099 100.527,145.72 101.93,145.72 102.184,145.466 102.184,143.154 102.85,142.489 103.815,142.489 104.008,142.296 104.008,141.096 104.497,140.607 106.069,140.607 106.68,141.218 106.68,142.361 107.264,142.945 107.264,143.472 106.947,143.789 106.585,143.789 106.197,144.177 106.197,144.424 105.664,144.958 105.664,146.166 v1(105.265,146.565)
  PWR13 w0.089: v1@102.662,148.214 103.327,147.549 103.327,147.245 v4(103.853,146.719)
  Bottom Layer w0.089: R110.1@103.378,146.776 103.796,146.776 v4(103.853,146.719) J1.86@105.182,146.719
B34_L8_N: J1.90 R113.2 U1.Y14 | length 27
  Top Layer w0.089: v9(104.775,145.034) 104.423,145.386 104.423,145.688 104.629,145.894 104.974,145.894 105.105,146.025 105.105,146.304 104.872,146.537 104.447,146.537 104.192,146.793 104.192,147.176 104.445,147.429 105.004,147.429 105.102,147.527 105.102,147.705 104.999,147.807 104.389,147.807 104.115,148.082 104.115,148.438 104.369,148.692 104.597,148.692 104.75,148.844 104.75,150.724 104.214,151.26 104.214,155.656 104.567,156.009 105.313,156.009 105.692,155.63 105.692,149.077 105.804,148.965 U1.Y14@106.065,148.965
  GND02 w0.089: v1(103.32,144.387) 103.968,145.034 v9(104.775,145.034)
  PWR13 w0.089: v1(103.32,144.387) 103.653,144.719 v4(103.853,144.719)
  Bottom Layer w0.089: R113.2@103.378,144.638 103.772,144.638 v4(103.853,144.719) J1.90@105.182,144.719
